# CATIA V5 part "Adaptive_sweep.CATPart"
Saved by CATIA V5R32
Part number: Part1
Bounding box of the stored display mesh (mm): x -106.531 to 0, y -4.546 to 2.643, z -53.351 to 74.079
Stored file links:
  D:\PROJECTS\Project 2022\CATIA V5 6R 2022\Resources\Part Files\c17_catia_v6_6r2022_prt\Adaptive_sweep.CATPart
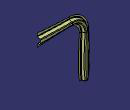
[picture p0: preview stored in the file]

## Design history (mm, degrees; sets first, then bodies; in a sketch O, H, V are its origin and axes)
Body1 (main body)
  Sketch1 on zx-plane, origin (0, 0, 0), H (-1, 0, 0), V (0, 0, 1)
    point P1 (0, 61.5796)
    line L1 (0, 61.5796) -> (65, 61.5796)
    line L2 (94.9999, 31.6495) -> (94.9999, -53.3505)
    point P2 (94.9999, -53.3505)
    arc A1 centre (64.9999, 31.5796) radius 30 from (65, 61.5796) to (94.9999, 31.6495) cw
    radius A1 = 30
    length L1 = 65
    length L2 = 85
    coincidence: P1 V
    horizontal: L1 H
    vertical: L2 V
    tangency: A1 L1, A1 L2
  Sketch2 on {plane type Normal, Curve Sketch1, RefPoint Sketch1.P2}, origin (-94.9999, 0, -53.3505), H (1, 0, 0), V (0, 1, 0)
    point P1 (-5.022, -3.8355)
    line L1 (-4.7817, -3.2105) -> (-2.9, 1.6817)
    point P2 (-2.522, 2.6645)
    line L2 (-5.8642, -3.8355) -> (-8.8642, -3.8355)
    point P3 (-8.8642, -3.8355)
    arc A1 centre (-1.5, 1.1433) radius 1.5 from (-2.9, 1.6817) to (-1.5, 2.6433) cw
    point P4 (-2.9, 1.6817)
    point P5 (-1.5, 2.6433)
    line L3 (-5.8642, -3.8355) -> (-4.7817, -3.2105)
    point P7 (-5.8642, -3.8355)
    point P8 (-4.7817, -3.2105)
    point P9 (5.022, -3.8355)
    point P10 (2.522, 2.6645)
    point P11 (8.8642, -3.8355)
    point P12 (2.9, 1.6817)
    point P13 (1.5, 2.6433)
    point P15 (5.8642, -3.8355)
    point P16 (4.7817, -3.2105)
    line L4 (4.7817, -3.2105) -> (2.9, 1.6817)
    line L5 (5.8642, -3.8355) -> (8.8642, -3.8355)
    arc A2 centre (1.5, 1.1433) radius 1.5 from (2.9, 1.6817) to (1.5, 2.6433) ccw
    line L6 (5.8642, -3.8355) -> (4.7817, -3.2105)
    line L7 (-1.5, 2.6433) -> (1.5, 2.6433)
    distance P2 P1 V = 6.5
    radius A1 = 1.5
    angle L2 L3 = 30
    length L3 = 1.25
    length L2 = 3
    length L7 = 3
    horizontal: L2 H
    coincidence: L1 P2, L2 P1, L1 P1
    tangency: A1 L1, L7 A1
    symmetry: P1 P9 V, P2 P10 V, P3 P11 V, P4 P12 V, P5 P13 V, P7 P15 V, P8 P16 V, L1 L4 V, L2 L5 V, A1 A2 V, L3 L6 V
  SweepSketch1: Spine Sketch1, Sketch Sketch2, ListSketches (a sketch; a sketch; a sketch; a sketch), SectionVertices ({point type OnCurve, Support Sketch1, Ratio 0}; Sketch1.P1; {point type OnCurve, Support Sketch1, Ratio 0.154867}; {point type OnCurve, Support Sketch1, Ratio 0.572067})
